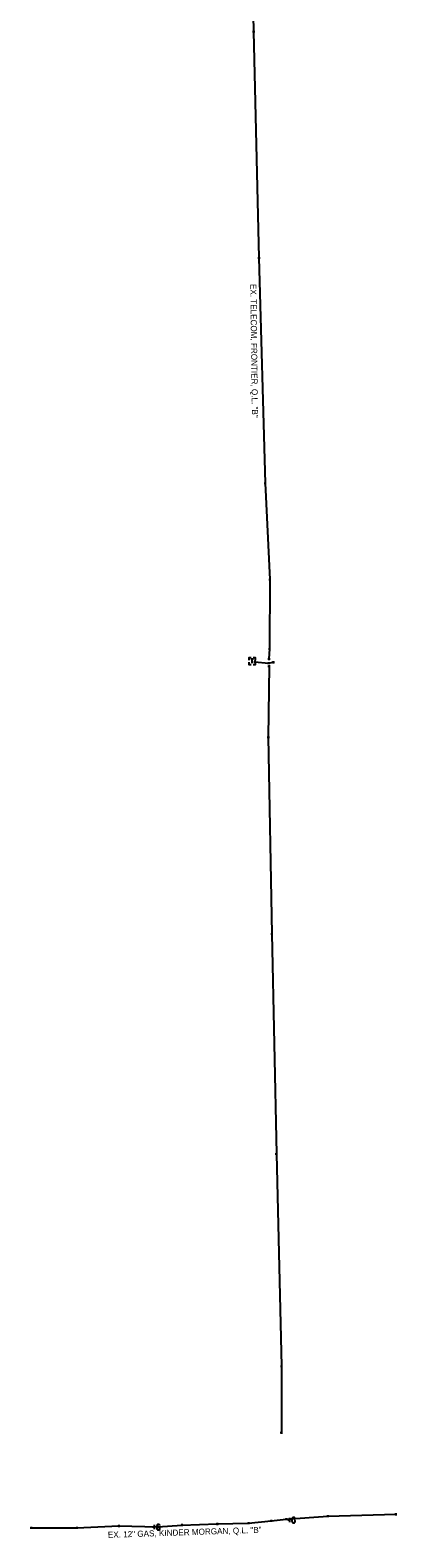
# Model space of a CAD drawing. Extents: x 2046588 to 2048646, y 455919 to 457871.
# Drawn here: x 2047568 to 2047738, y 455919 to 456615 of the extents above; entities that cross this region are included whole.
import ezdxf

# ---------------------------------------------------------------- set-up
doc = ezdxf.new("R2010")
doc.units = 0
for name, color, linetype in [('CM_Corridor_Top_Mesh', 7, 'Continuous'), ('MD_P_Surface_Curb', 7, 'Continuous'), ('MD_P_Surface_Non-Reinforced_Concrete_Pavement', 7, 'Continuous'), ('UT_P_Gas', 7, 'Continuous'), ('UT_X_FO', 7, 'Continuous'), ('UT_X_Gas', 7, 'Continuous'), ('UT_X_Overhead_Telecom', 7, 'Continuous')]:
    doc.layers.add(name, color=color, linetype=linetype)

msp = doc.modelspace()

# ---------------------------------------------------------------- linework, layer by layer
at = {"layer": 'CM_Corridor_Top_Mesh'}
for points in [[(2047664.23, 456756.81), (2047669.8, 456757.54), (2047669.74, 456705.78), (2047671.58, 456614.77), (2047674.06, 456510.32), (2047676.92, 456406.31), (2047679.08, 456361.81), (2047678.89, 456329.69), (2047678.68, 456325.08)], [(2047672.12, 456323.81), (2047678.51, 456323.15), (2047680.65, 456323.55)], [(2047678.71, 456321.72), (2047678.37, 456289.04), (2047679.96, 456198.19), (2047682.08, 456096.68), (2047684.47, 455998.58), (2047684.39, 455967.92)]]:
    msp.add_lwpolyline(points, dxfattribs=at)
at = {"layer": 'UT_P_Gas'}
for p, q in [((2047670.27, 456325.08), (2047671.57, 456325.08)), ((2047670.92, 456323.08), (2047670.92, 456325.08)), ((2047670.92, 456324.08), (2047670.92, 456324.08))]:
    msp.add_line(p, q, dxfattribs=at)
for points in [[(2047670.52, 456325.58), (2047669.42, 456325.58), (2047669.42, 456324.48)], [(2047669.42, 456323.68), (2047669.42, 456322.58), (2047670.52, 456322.58)], [(2047672.42, 456324.48), (2047672.42, 456325.58), (2047671.32, 456325.58)], [(2047671.32, 456322.58), (2047672.42, 456322.58), (2047672.42, 456323.68)]]:
    msp.add_lwpolyline(points, dxfattribs=at)
at = {"layer": 'UT_X_FO'}
for p, q in [((2047625.88, 455924.29), (2047624.93, 455924.29)), ((2047625.88, 455923.29), (2047625.88, 455925.29)), ((2047688.25, 455927.53), (2047687.3, 455927.53)), ((2047688.25, 455926.53), (2047688.25, 455928.53))]:
    msp.add_line(p, q, dxfattribs=at)
for points in [[(2047628.36, 455925.05), (2047628.34, 455925.14), (2047628.28, 455925.24), (2047628.18, 455925.34), (2047628.04, 455925.46), (2047627.94, 455925.5), (2047627.87, 455925.52), (2047627.75, 455925.54), (2047627.51, 455925.54), (2047627.41, 455925.52), (2047627.35, 455925.5), (2047627.27, 455925.46), (2047627.12, 455925.34), (2047627.02, 455925.2), (2047626.96, 455925.05), (2047626.92, 455924.83), (2047626.88, 455924.51), (2047626.88, 455924.1), (2047626.9, 455923.77), (2047626.98, 455923.51), (2047627.1, 455923.27), (2047627.2, 455923.2), (2047627.31, 455923.12), (2047627.53, 455923.04), (2047627.75, 455923.04), (2047627.96, 455923.08), (2047628.04, 455923.12), (2047628.12, 455923.16), (2047628.2, 455923.23), (2047628.28, 455923.35), (2047628.36, 455923.53), (2047628.36, 455924.02), (2047627.94, 455924.02)], [(2047690.73, 455928.28), (2047690.71, 455928.38), (2047690.65, 455928.48), (2047690.55, 455928.58), (2047690.41, 455928.7), (2047690.32, 455928.74), (2047690.24, 455928.76), (2047690.12, 455928.78), (2047689.88, 455928.78), (2047689.78, 455928.76), (2047689.73, 455928.74), (2047689.65, 455928.7), (2047689.49, 455928.58), (2047689.39, 455928.44), (2047689.33, 455928.28), (2047689.29, 455928.07), (2047689.25, 455927.75), (2047689.25, 455927.34), (2047689.27, 455927), (2047689.35, 455926.75), (2047689.47, 455926.51), (2047689.57, 455926.43), (2047689.69, 455926.35), (2047689.9, 455926.28), (2047690.12, 455926.28), (2047690.34, 455926.31), (2047690.41, 455926.35), (2047690.49, 455926.39), (2047690.57, 455926.47), (2047690.65, 455926.59), (2047690.73, 455926.77), (2047690.73, 455927.26), (2047690.32, 455927.26)]]:
    msp.add_lwpolyline(points, dxfattribs=at)
at = {"layer": 'UT_X_Gas'}
for p, q in [((2047671.08, 456614.77), (2047672.08, 456614.77)), ((2047671.58, 456615.27), (2047671.58, 456614.27)), ((2047671.58, 456614.77), (2047671.58, 456614.77)), ((2047673.56, 456510.32), (2047674.56, 456510.32)), ((2047674.06, 456510.82), (2047674.06, 456509.82)), ((2047674.06, 456510.32), (2047674.06, 456510.32)), ((2047676.42, 456406.31), (2047677.42, 456406.31)), ((2047676.92, 456406.81), (2047676.92, 456405.81)), ((2047676.92, 456406.31), (2047676.92, 456406.31)), ((2047678.58, 456361.81), (2047679.58, 456361.81)), ((2047679.08, 456362.31), (2047679.08, 456361.31)), ((2047679.08, 456361.81), (2047679.08, 456361.81)), ((2047678.39, 456329.69), (2047679.39, 456329.69)), ((2047678.89, 456330.19), (2047678.89, 456329.19)), ((2047678.89, 456329.69), (2047678.89, 456329.69)), ((2047671.62, 456323.81), (2047672.62, 456323.81)), ((2047672.12, 456324.31), (2047672.12, 456323.31)), ((2047672.12, 456323.81), (2047672.12, 456323.81)), ((2047678.01, 456323.15), (2047679.01, 456323.15)), ((2047678.18, 456325.08), (2047679.18, 456325.08)), ((2047678.21, 456321.72), (2047679.21, 456321.72)), ((2047678.51, 456323.65), (2047678.51, 456322.65)), ((2047678.51, 456323.15), (2047678.51, 456323.15)), ((2047678.68, 456325.58), (2047678.68, 456324.58)), ((2047678.68, 456325.08), (2047678.68, 456325.08)), ((2047678.71, 456322.22), (2047678.71, 456321.22)), ((2047678.71, 456321.72), (2047678.71, 456321.72)), ((2047680.15, 456323.55), (2047681.15, 456323.55)), ((2047680.65, 456324.05), (2047680.65, 456323.05)), ((2047680.65, 456323.55), (2047680.65, 456323.55)), ((2047677.87, 456289.04), (2047678.87, 456289.04)), ((2047678.37, 456289.54), (2047678.37, 456288.54)), ((2047678.37, 456289.04), (2047678.37, 456289.04)), ((2047679.46, 456198.19), (2047680.46, 456198.19)), ((2047679.96, 456198.69), (2047679.96, 456197.69)), ((2047679.96, 456198.19), (2047679.96, 456198.19)), ((2047681.58, 456096.68), (2047682.58, 456096.68)), ((2047682.08, 456097.18), (2047682.08, 456096.18)), ((2047682.08, 456096.68), (2047682.08, 456096.68)), ((2047683.97, 455998.58), (2047684.97, 455998.58)), ((2047684.47, 455999.08), (2047684.47, 455998.08)), ((2047684.47, 455998.58), (2047684.47, 455998.58)), ((2047683.89, 455967.92), (2047684.89, 455967.92)), ((2047684.39, 455968.42), (2047684.39, 455967.42)), ((2047684.39, 455967.92), (2047684.39, 455967.92)), ((2047568.49, 455924.01), (2047569.49, 455924.01)), ((2047568.99, 455924.51), (2047568.99, 455923.51)), ((2047568.99, 455924.01), (2047568.99, 455924.01)), ((2047589.55, 455923.96), (2047590.55, 455923.96)), ((2047590.05, 455924.46), (2047590.05, 455923.46)), ((2047590.05, 455923.96), (2047590.05, 455923.96)), ((2047608.91, 455924.84), (2047609.91, 455924.84)), ((2047609.41, 455925.34), (2047609.41, 455924.34)), ((2047609.41, 455924.84), (2047609.41, 455924.84)), ((2047626.84, 455924.38), (2047627.84, 455924.38)), ((2047627.34, 455924.88), (2047627.34, 455923.88)), ((2047627.34, 455924.38), (2047627.34, 455924.38)), ((2047637.94, 455925.27), (2047638.94, 455925.27)), ((2047638.44, 455925.77), (2047638.44, 455924.77)), ((2047638.44, 455925.27), (2047638.44, 455925.27)), ((2047654.32, 455925.77), (2047655.32, 455925.77)), ((2047654.82, 455926.27), (2047654.82, 455925.27)), ((2047654.82, 455925.77), (2047654.82, 455925.77)), ((2047668.74, 455926.16), (2047669.74, 455926.16)), ((2047669.24, 455926.66), (2047669.24, 455925.66)), ((2047669.24, 455926.16), (2047669.24, 455926.16)), ((2047679.22, 455927.17), (2047680.22, 455927.17)), ((2047679.72, 455927.67), (2047679.72, 455926.67)), ((2047679.72, 455927.17), (2047679.72, 455927.17)), ((2047686.17, 455927.96), (2047687.17, 455927.96)), ((2047686.67, 455928.46), (2047686.67, 455927.46)), ((2047686.67, 455927.96), (2047686.67, 455927.96)), ((2047705.27, 455929.35), (2047706.27, 455929.35)), ((2047705.77, 455929.85), (2047705.77, 455928.85)), ((2047705.77, 455929.35), (2047705.77, 455929.35)), ((2047736.66, 455930.21), (2047737.66, 455930.21)), ((2047737.16, 455930.71), (2047737.16, 455929.71)), ((2047737.16, 455930.21), (2047737.16, 455930.21))]:
    msp.add_line(p, q, dxfattribs=at)
at = {"layer": 'UT_X_Overhead_Telecom'}
msp.add_lwpolyline([(2047568.99, 455924.01), (2047590.05, 455923.96), (2047609.41, 455924.84), (2047627.34, 455924.38), (2047638.44, 455925.27), (2047654.82, 455925.77), (2047669.24, 455926.16), (2047679.72, 455927.17), (2047686.67, 455927.96), (2047705.77, 455929.35), (2047737.16, 455930.21)], dxfattribs=at)

# ---------------------------------------------------------------- texts
at = {"layer": 'MD_P_Surface_Curb'}
msp.add_text('EX. 12" GAS, KINDER MORGAN, Q.L. "B"', height=2.8, rotation=1.90203, dxfattribs=at).set_placement((2047604.37, 455919.34))
at = {"layer": 'MD_P_Surface_Non-Reinforced_Concrete_Pavement'}
msp.add_text('EX. TELECOM, FRONTIER, Q.L. "B"', height=2.8, rotation=270.70308, dxfattribs=at).set_placement((2047670.05, 456498.19))

doc.saveas('drawing.dxf')
